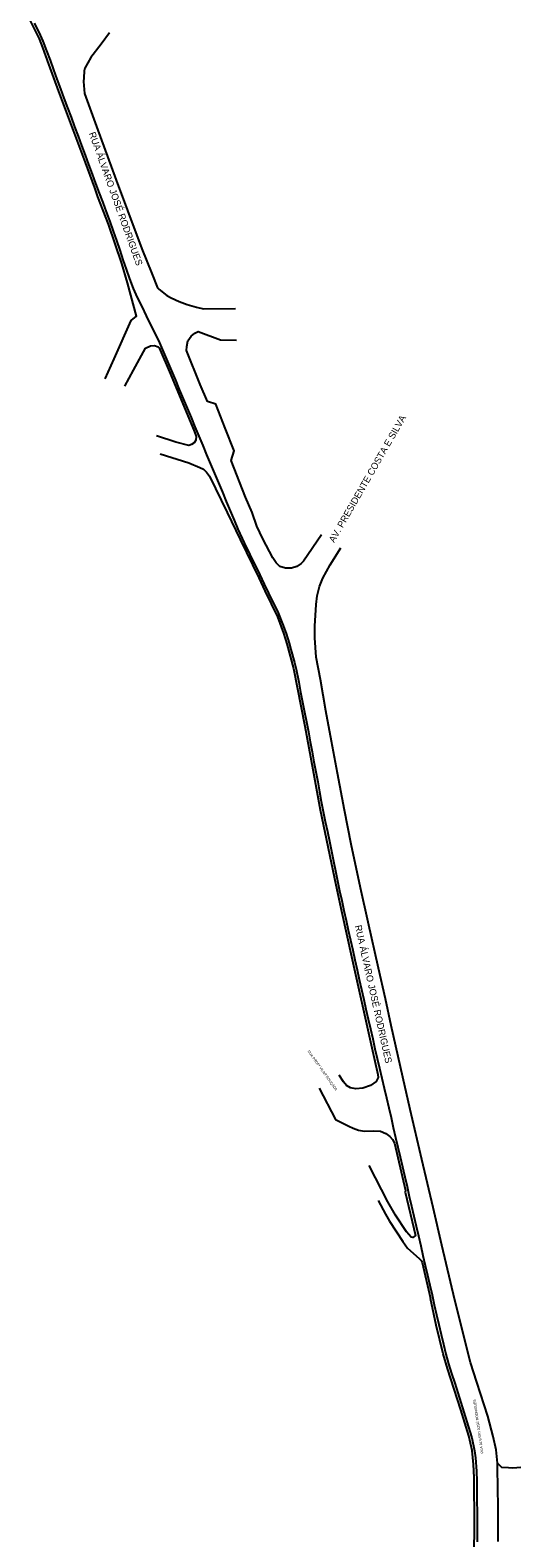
# Model space of a CAD drawing. Extents: x 656692 to 673945, y 7585994 to 7599066.
# Drawn here: x 658934 to 659412, y 7588583 to 7590050 of the extents above; entities that cross this region are included whole.
import ezdxf

# ---------------------------------------------------------------- set-up
doc = ezdxf.new("R2010")
doc.units = 0
for name, color, linetype in [('LOGRADOURO', 7, 'Continuous'), ('LOGRADOURO_TEXTO', 7, 'Continuous'), ('TUBO_PEAD_GN_63', 7, 'Continuous')]:
    doc.layers.add(name, color=color, linetype=linetype)

msp = doc.modelspace()

# ---------------------------------------------------------------- linework, layer by layer
at = {"layer": 'LOGRADOURO'}
for points in [[(659006.8, 7589711.1), (659015.7, 7589730.5), (659032.1, 7589767.8), (659037.3, 7589772), (659028.8, 7589804.3), (659023.1, 7589823.1), (659010, 7589861.5), (658999.9, 7589888.2), (658996.7, 7589896.9), (658987.6, 7589921.3), (658976.1, 7589952.6), (658961.9, 7589990.6), (658952.1, 7590017.1), (658946.3, 7590033.5), (658942.9, 7590041.9), (658939.2, 7590049.7), (658933.9, 7590060.1)], [(659011, 7590047.5), (659002.9, 7590036.7), (658993.1, 7590023.5), (658987.2, 7590013.3), (658986.6, 7590010.6), (658986, 7590003.8), (658985.7, 7590000.3), (658986.9, 7589988.6), (658998.6, 7589956.5), (659017.6, 7589904.4), (659028.8, 7589874.9), (659042.7, 7589837.6), (659052.4, 7589813.4), (659058, 7589799.4), (659059.1, 7589798.2), (659066.8, 7589792), (659071.3, 7589789.8), (659079, 7589786.1), (659086.6, 7589783.3), (659095.8, 7589780.6), (659102.6, 7589779.1), (659133.7, 7589779.4)], [(659217.4, 7589559.1), (659199.9, 7589533.4), (659197.6, 7589531.3), (659193.4, 7589528.3), (659188.3, 7589526.7), (659182.6, 7589526.7), (659176.9, 7589528.4), (659173.3, 7589531.8), (659170.1, 7589536.7), (659160.3, 7589555.4), (659154.7, 7589567.6), (659150, 7589580.8), (659143.4, 7589595.8), (659129.5, 7589631.5), (659132.4, 7589641), (659123.7, 7589662.9), (659114.6, 7589686.3), (659106.4, 7589688.9), (659099.5, 7589705.4), (659086, 7589738.6), (659086.3, 7589742.3), (659087.5, 7589747.9), (659090.6, 7589752.5), (659094.1, 7589755.5), (659097.3, 7589756.9), (659119.3, 7589749), (659134.7, 7589748.7)], [(659026.1, 7589703.9), (659034.6, 7589719.5), (659046.2, 7589740.8), (659051, 7589743.1), (659054.8, 7589743.3), (659058.6, 7589742), (659059.5, 7589741), (659070.4, 7589715.5), (659094, 7589659.4), (659095.6, 7589654.8), (659095.1, 7589651.2), (659093.5, 7589648.5), (659090.9, 7589647), (659088.5, 7589646), (659075.8, 7589649.4), (659057, 7589655.4)], [(659060.5, 7589637.9), (659088.3, 7589629.1), (659099.1, 7589624.8), (659102.5, 7589623), (659105.6, 7589620), (659108.5, 7589616.1), (659125.6, 7589580.8), (659138.2, 7589554.5), (659156.5, 7589517.3), (659162.4, 7589504.7), (659174.8, 7589479.3), (659180.6, 7589463.3), (659183.9, 7589453.1), (659190.1, 7589429.1), (659201.2, 7589372.9), (659209.1, 7589330.9), (659216.3, 7589291.5), (659231.5, 7589218.5), (659236.9, 7589193), (659246.8, 7589148.9), (659266.6, 7589060), (659272.5, 7589033.9), (659272.6, 7589030.9), (659270.6, 7589027.3), (659265.2, 7589023.3), (659257.7, 7589020.7), (659250.8, 7589019.9), (659245.6, 7589021), (659241.7, 7589023.4), (659238.8, 7589026.9), (659234.6, 7589033.4)], [(659296.6, 7589031.3), (659285.4, 7589081.5), (659279.7, 7589107.5), (659273, 7589137.6), (659263.1, 7589182.1), (659255.5, 7589215.7), (659246.3, 7589258.1), (659240, 7589291.3), (659233, 7589327.1), (659227.1, 7589358.4), (659221.8, 7589388), (659216.4, 7589418.2), (659212.3, 7589440), (659211.1, 7589458.8), (659211.1, 7589470.2), (659212.2, 7589491.2), (659213.4, 7589499.7), (659215.5, 7589508.8), (659218.9, 7589517), (659226.1, 7589529.8), (659236.3, 7589546.5)], [(659389, 7588655.7), (659387.5, 7588668.8), (659384.8, 7588681.8), (659379.3, 7588701.6), (659368.9, 7588734.7), (659362.7, 7588753.7), (659347.2, 7588814.4), (659334.7, 7588867.8), (659326.1, 7588904.6), (659315.3, 7588951.1), (659303.7, 7589000), (659296.6, 7589031.3)], [(659215.3, 7589020.8), (659231.3, 7588990.1), (659244.2, 7588983.6), (659248.4, 7588981.7), (659253.7, 7588979.8), (659259.4, 7588978.8), (659267.8, 7588979.2), (659274.8, 7588978.8), (659280.2, 7588976.7), (659284.2, 7588973.7), (659286.8, 7588970.8), (659288.5, 7588967.2), (659299.3, 7588921), (659299, 7588919.4), (659309, 7588877.4), (659306.4, 7588875.2), (659304.7, 7588875.6), (659300.2, 7588880.8), (659289.7, 7588897.1), (659282.1, 7588910.2), (659263.9, 7588945.4)], [(659272.6, 7588911.2), (659279.7, 7588898.1), (659283.8, 7588891.4), (659296.7, 7588871.3), (659301.4, 7588865.1), (659312.5, 7588855), (659314.9, 7588852.5), (659315.4, 7588851.1), (659323.5, 7588816)], [(659366.3, 7588567.6), (659366.4, 7588595.2), (659366.2, 7588641.9), (659365.6, 7588654.6), (659364.2, 7588668.2), (659360.8, 7588682.4), (659353.1, 7588707.7), (659340.2, 7588747.8), (659336, 7588762), (659329.3, 7588790.1), (659323.5, 7588816)], [(659389.4, 7588617.4), (659389.3, 7588627.3), (659389, 7588655.7)], [(659389, 7588655.7), (659392.8, 7588651.9), (659399.5, 7588651.4), (659403.9, 7588651.2), (659411.6, 7588651.8)], [(659389.6, 7588579.5), (659389.4, 7588617.4)]]:
    msp.add_lwpolyline(points, dxfattribs=at)
at = {"layer": 'TUBO_PEAD_GN_63'}
msp.add_lwpolyline([(658937.8, 7590057.1), (658942.3, 7590048.3), (658946.3, 7590039.4), (658949.9, 7590030.2), (658953.2, 7590020.9), (658956.5, 7590011.7), (658959.9, 7590002.4), (658963.3, 7589993.2), (658966.8, 7589984), (658970.2, 7589974.8), (658973.7, 7589965.5), (658977.2, 7589956.3), (658980.6, 7589947.1), (658984, 7589937.9), (658987.4, 7589928.6), (658990.8, 7589919.4), (658994.2, 7589910.2), (658997.6, 7589900.9), (659001, 7589891.7), (659004.5, 7589882.5), (659008, 7589873.3), (659011.5, 7589864.1), (659014.7, 7589854.8), (659017.9, 7589845.5), (659021.1, 7589836.2), (659024.2, 7589826.8), (659027.4, 7589817.5), (659030.6, 7589808.2), (659034.3, 7589798.9), (659038.1, 7589790.1), (659042.5, 7589781.2), (659046.8, 7589772.4), (659051.2, 7589763.6), (659055.5, 7589754.7), (659059.8, 7589745.9), (659063.7, 7589736.8), (659067.6, 7589727.8), (659071.4, 7589718.7), (659075.3, 7589709.7), (659079.1, 7589700.6), (659082.9, 7589691.5), (659086.7, 7589682.5), (659090.5, 7589673.4), (659094.3, 7589664.3), (659098.1, 7589655.2), (659101.9, 7589646.2), (659105.7, 7589637.1), (659109.6, 7589628), (659113.4, 7589618.9), (659117.2, 7589609.8), (659121, 7589600.8), (659124.8, 7589591.7), (659128.6, 7589582.6), (659132.4, 7589573.5), (659136.2, 7589564.5), (659140.2, 7589555.5), (659144.5, 7589546.6), (659146.7, 7589542.2), (659148.8, 7589537.8), (659153.2, 7589529), (659157.5, 7589520.1), (659161.7, 7589511.2), (659166, 7589502.3), (659170.3, 7589493.5), (659174.6, 7589484.7), (659176, 7589481.6), (659179.7, 7589472.5), (659183, 7589463.2), (659186, 7589453.8), (659187.8, 7589447.5), (659191.1, 7589434.8), (659192.8, 7589428.4), (659195.3, 7589415.6), (659197.2, 7589405.9), (659199.1, 7589396.3), (659201, 7589386.6), (659202.9, 7589377), (659204.8, 7589367.3), (659206.6, 7589357.6), (659208.4, 7589348), (659210.2, 7589338.3), (659212, 7589328.6), (659213.8, 7589318.9), (659215.6, 7589309.2), (659217.3, 7589299.6), (659219.2, 7589289.9), (659221.2, 7589280.2), (659223.2, 7589270.6), (659225.2, 7589261), (659227.2, 7589251.3), (659229.2, 7589241.7), (659231.2, 7589232.1), (659233.2, 7589222.4), (659235.2, 7589212.8), (659237.2, 7589203.2), (659239.3, 7589193.5), (659241.4, 7589183.9), (659243.6, 7589174.3), (659245.7, 7589164.7), (659247.9, 7589155.1), (659250, 7589145.5), (659252.2, 7589135.9), (659254.3, 7589126.3), (659256.4, 7589116.7), (659258.6, 7589107.1), (659260.7, 7589097.5), (659262.9, 7589087.9), (659265.2, 7589078.3), (659267.4, 7589068.7), (659269.6, 7589059.1), (659271.8, 7589049.5), (659274.1, 7589040), (659276.3, 7589030.4), (659278.5, 7589020.8), (659280.8, 7589011.2), (659283, 7589001.6), (659285.2, 7588992), (659287.4, 7588982.4), (659289.7, 7588972.8), (659291.9, 7588963.3), (659294.1, 7588953.7), (659296.4, 7588944.1), (659298.6, 7588934.5), (659300.8, 7588924.9), (659303, 7588915.3), (659305.2, 7588905.7), (659307.5, 7588896.1), (659309.7, 7588886.5), (659311.9, 7588877), (659314.1, 7588867.4), (659316.3, 7588857.8), (659318.5, 7588848.2), (659320.7, 7588838.6), (659322.9, 7588829), (659325.1, 7588819.4), (659327.3, 7588809.8), (659329.5, 7588800.2), (659331.6, 7588790.6), (659333.9, 7588781), (659336.2, 7588771.5), (659338.6, 7588761.9), (659341.3, 7588752.4), (659344.2, 7588743), (659347.2, 7588733.7), (659350.2, 7588724.3), (659353.2, 7588714.9), (659356.2, 7588705.5), (659359.1, 7588696.1), (659361.9, 7588686.7), (659363.8, 7588680.4), (659366.5, 7588667.6), (659367.5, 7588661), (659368.5, 7588648), (659368.8, 7588638.2), (659368.9, 7588628.3), (659368.9, 7588618.5), (659369, 7588608.7), (659369, 7588598.8), (659369, 7588589), (659369, 7588579.1)], dxfattribs=at)

# ---------------------------------------------------------------- texts
at = {"layer": 'LOGRADOURO_TEXTO'}
for s, height, rotation, p in [('RUA ÁLVARO JOSÉ RODRIGUES', 6.562, 289.7897, (658990.9, 7589949.8)), ('AV. PRESIDENTE COSTA E SILVA', 6.562, 60.1305, (659229.9, 7589551)), ('RUA ÁLVARO JOSÉ RODRIGUES', 6.562, 282.6133, (659249.9, 7589178.6)), ('RUA PROFº VILAR BOUÇADA', 2.461, 305.6555, (659203.7, 7589056.5)), ('RUA ÁLVARO JOSÉ RODRIGUES', 2.461, 98.1829, (659375.2, 7588665.3))]:
    msp.add_text(s, height=height, rotation=rotation, dxfattribs=at).set_placement(p)

doc.saveas('drawing.dxf')
